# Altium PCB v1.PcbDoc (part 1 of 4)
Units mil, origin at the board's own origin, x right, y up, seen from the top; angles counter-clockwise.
Board outline 3043 x 5109 mil, 2 copper layers (Top Layer, Bottom Layer), stack 62 mil thick; 379 components, 219 nets, 963 pads, 1099 vias.
Unrouted connection lines stored in the file: 1.
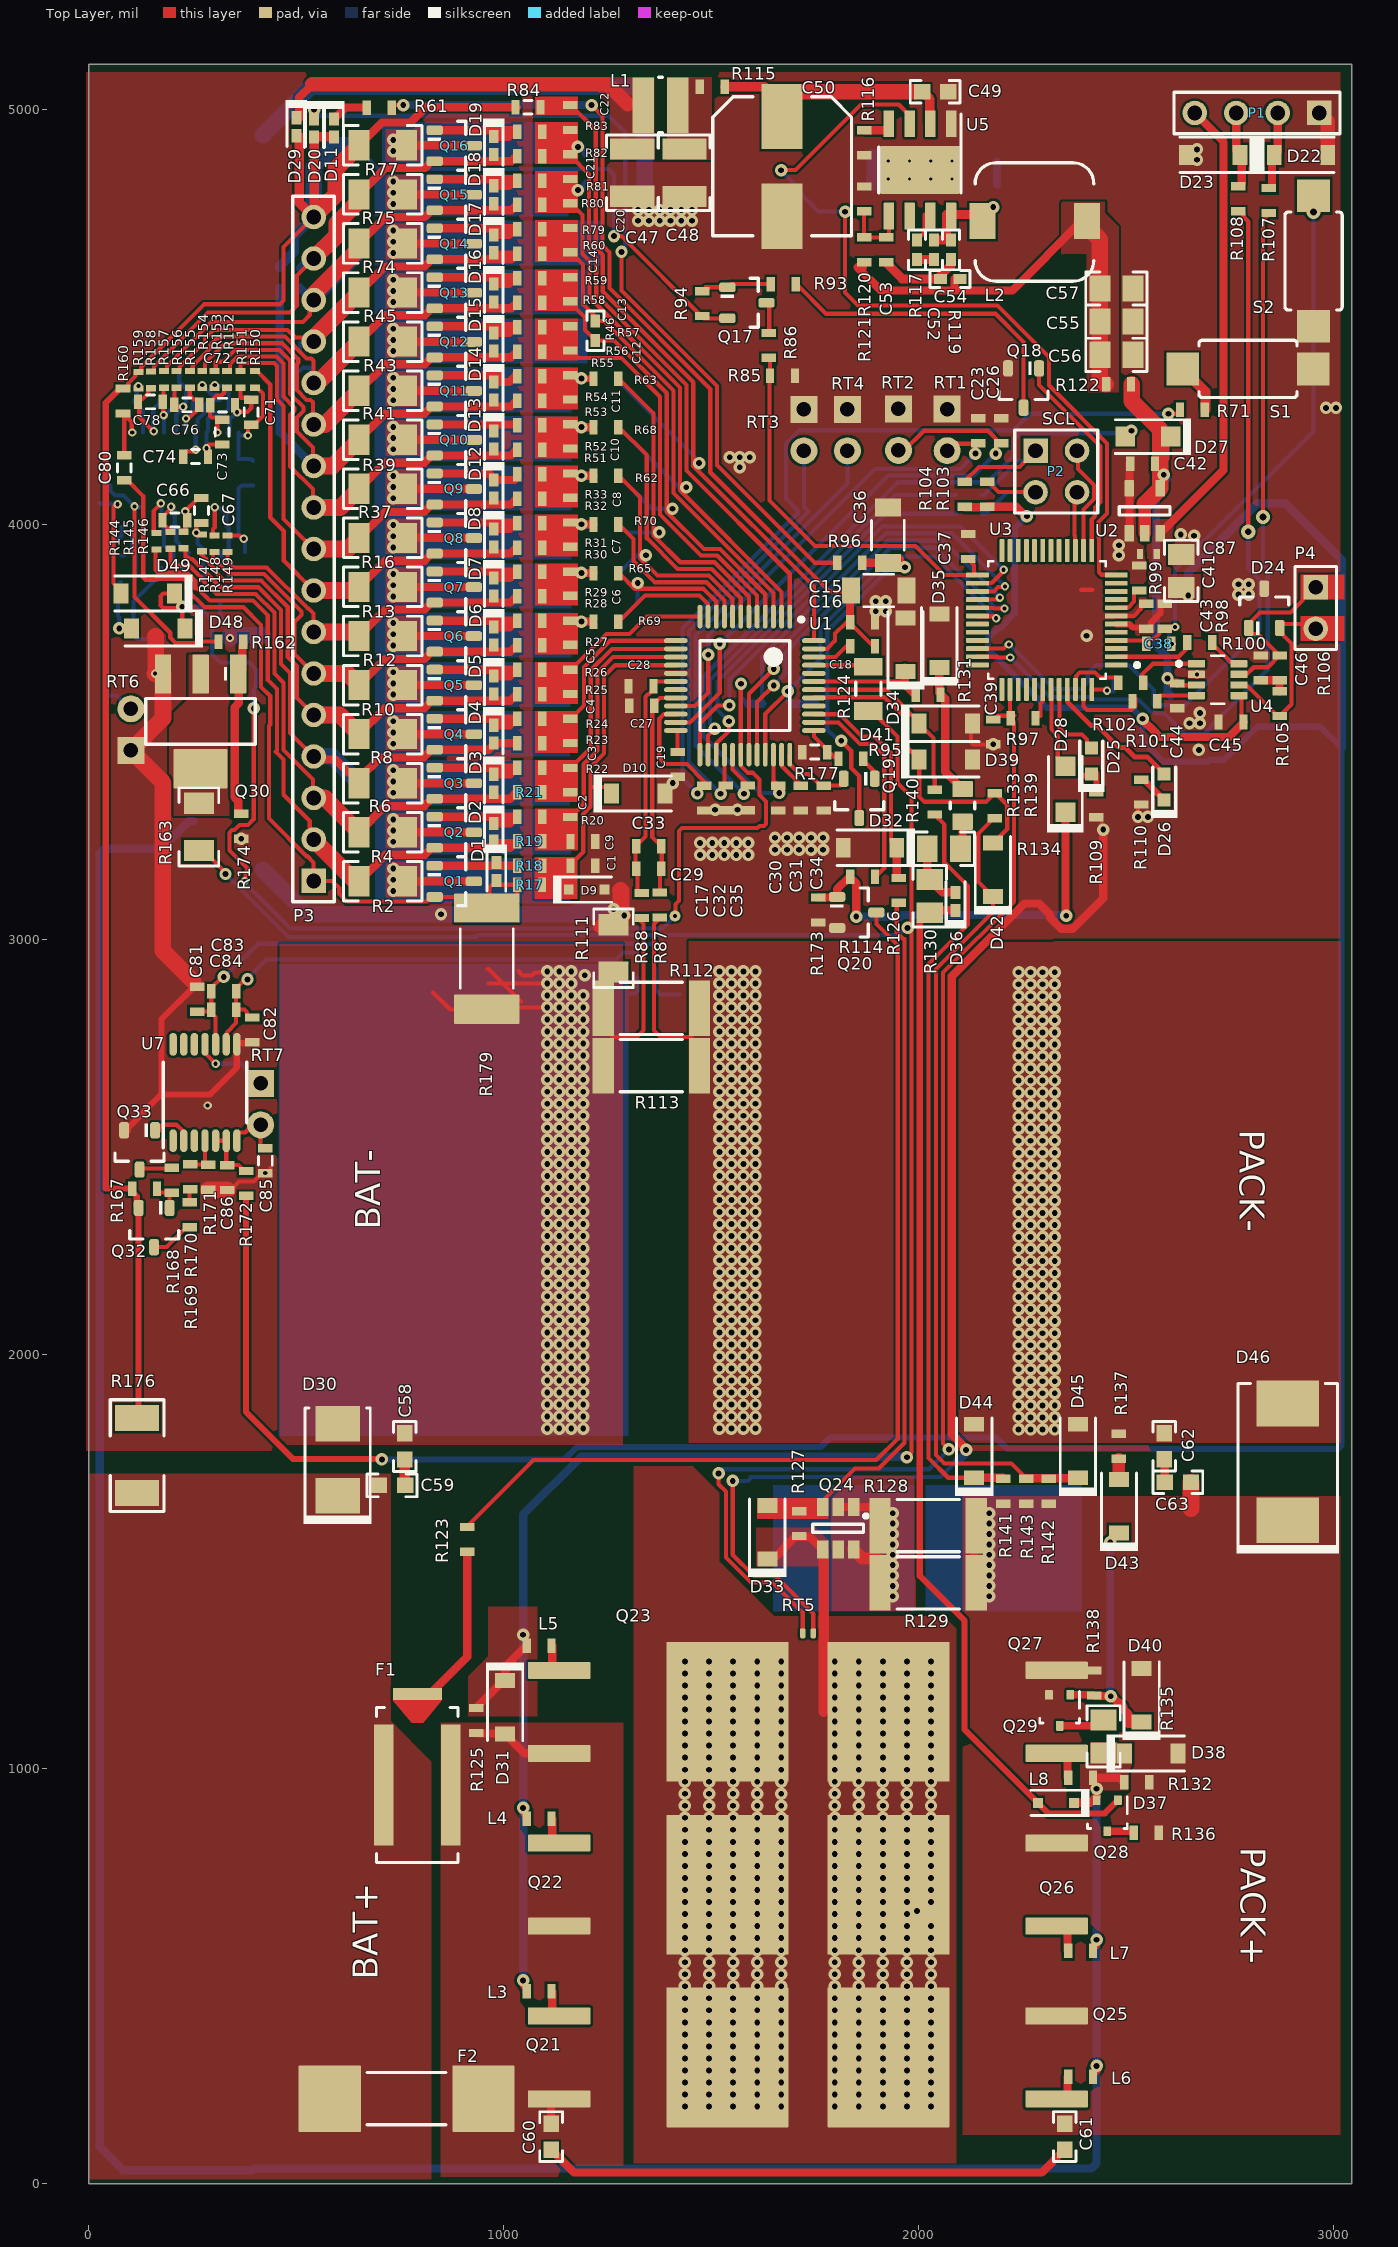
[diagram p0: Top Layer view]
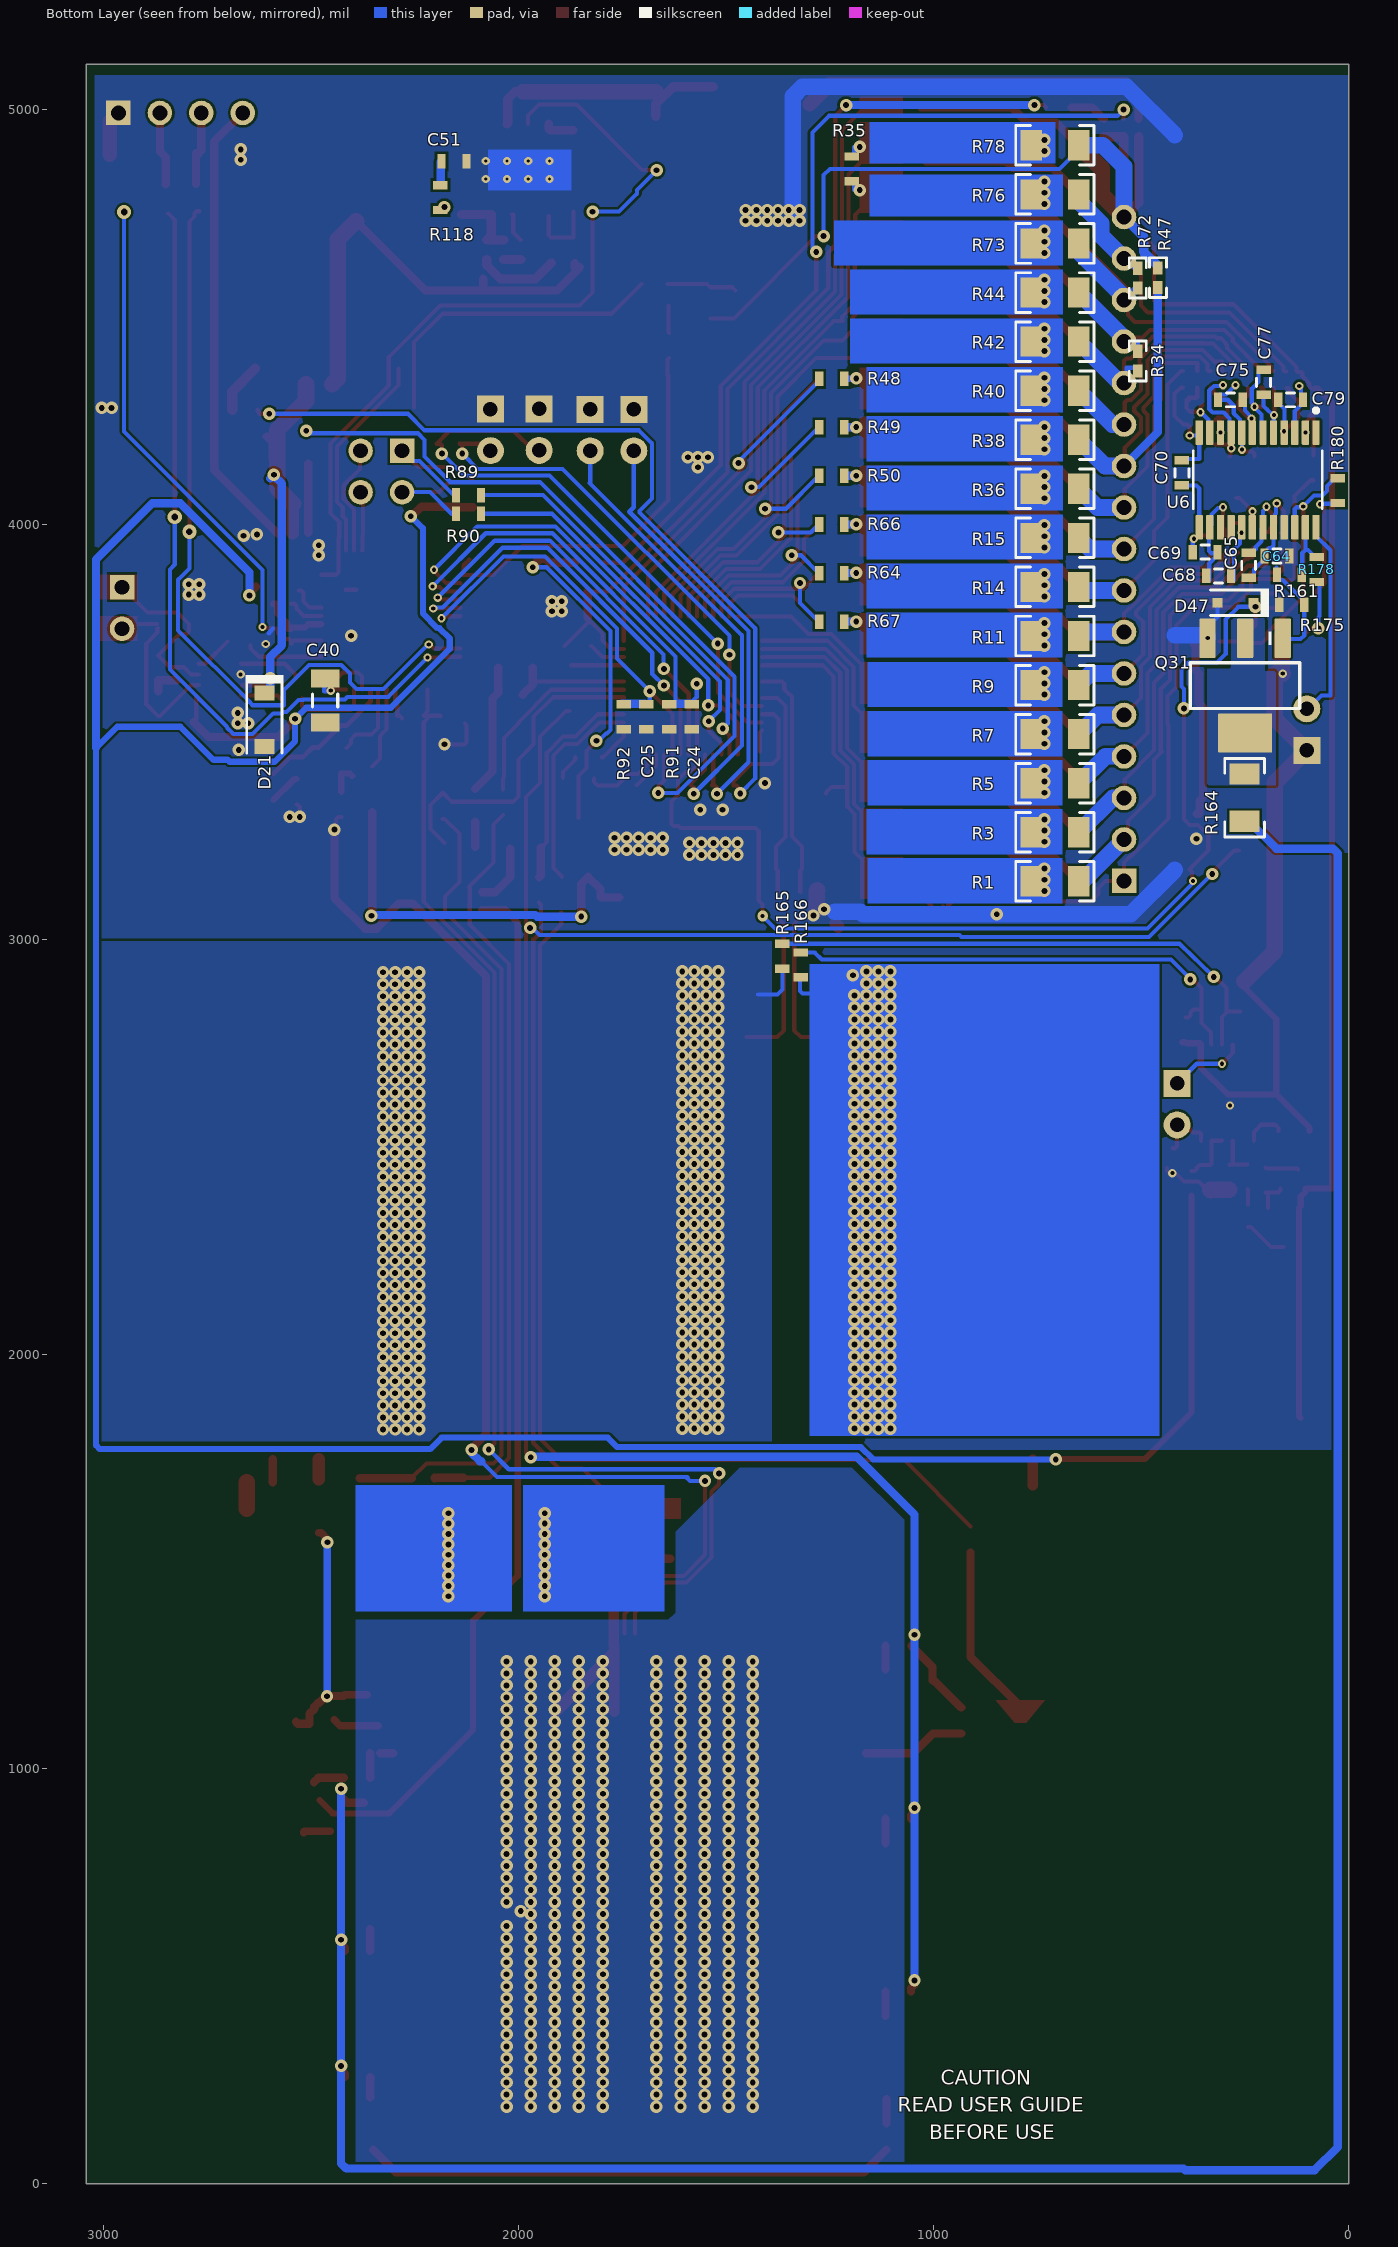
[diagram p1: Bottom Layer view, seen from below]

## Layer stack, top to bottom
Top Solder: solder mask 0.4, Solder Resist, Dk 3.5
Top Layer: signal copper 1.4
Dielectric1: core 59.2, FR-4, Dk 4.8
Bottom Layer: signal copper 1.4
Bottom Solder: solder mask 0.4, Solder Resist, Dk 3.5

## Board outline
0,0 0,5109 3043,5109 3043,0

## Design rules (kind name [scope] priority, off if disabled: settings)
AcuteAngle [All] p1: minimum=4.50000000000000E+0001 checktracksonly=FALSE
AssemblyTestPointUsage [All] p1: valid=2
BoardOutlineClearance BoardOutlineClearance_MountingHoles [OnCopper and InComponentClass('Mounting Holes')] p1 off: gap=40 ignorepadtopadclearanceinfootprint=FALSE
BoardOutlineClearance BoardOutlineClearance_Poly [OnCopper and IsPoly] p2 off: gap=25 ignorepadtopadclearanceinfootprint=FALSE
BoardOutlineClearance [OnCopper and Not InComponentClass('Logo') and not InComponentClass('FiducialMark') and not InRegion(1000,500,4000,800) and not InPoly] p3 off: gap=75 ignorepadtopadclearanceinfootprint=FALSE
Clearance Clearance_Keepouts [((IsTrack Or IsArc) And Not InPoly) And IsFree and IsKeepOut vs ((IsTrack Or IsArc) And Not InPoly) And IsFree and IsKeepOut] p1: gap=10 ignorepadtopadclearanceinfootprint=FALSE
Clearance Clearance_Poly [InPolygon] p2: gap=6 ignorepadtopadclearanceinfootprint=FALSE
Clearance Clearance_FiducialMark [IsKeepOut and InComponentClass('FiducialMark') vs IsPad and InComponentClass('FiducialMark')] p3: gap=0 ignorepadtopadclearanceinfootprint=FALSE
Clearance [All] p4: gap=6 ignorepadtopadclearanceinfootprint=FALSE
ComponentClearance ComponentClearance_MountingHoles_FiducialMarks [InComponentClass('Mounting Holes') vs InComponentClass('FiducialMark')] p1: gap=10 collisioncheckmode=3 verticalgap=10 showdistances=FALSE
ComponentClearance ComponentClearance_Shunt [InComponentClass('Header') vs InComponentClass('Shunt')] p2: gap=10 collisioncheckmode=3 verticalgap=10 showdistances=FALSE
ComponentClearance ComponentClearance_Logo [InComponentClass('Logo')] p3: gap=50 collisioncheckmode=3 verticalgap=10 showdistances=FALSE
ComponentClearance ComponentClearance_ScrewToNut [(HasFootprint('NY PMS 440 0025 PH')) vs (HasFootprint('Keystone_1902C'))] p4: gap=5 collisioncheckmode=3 verticalgap=10 showdistances=FALSE
ComponentClearance ComponentClearance_MountingHoles [InComponentClass('Mounting Holes')] p5: gap=6 collisioncheckmode=3 verticalgap=100000 showdistances=FALSE
ComponentClearance ComponentClearance_SmallPassives [HasFootprint('0201*') or HasFootprint('0402*') or HasFootprint('0508') or HasFootprint('0603*') or HasFootprint('0612') or HasFootprint('0805*') or HasFootprint('0815*') or HasFootprint('0830*') or HasFootprint('1206*') or HasFootprint('1210*') or HasFootprint('1808*') or HasFootprint('1812*') or HasFootprint('1825*') or HasFootprint('2010*') or HasFootprint('2220*') or HasFootprint('2225*') or HasFootprint('2512*') or HasFootprint('2728*') or HasFootprint('3518*') vs HasFootprint('0201*') or HasFootprint('0402*') or HasFootprint('0508') or HasFootprint('0603*') or HasFootprint('0612') or HasFootprint('0805*') or HasFootprint('0815*') or HasFootprint('0830*') or HasFootprint('1206*') or HasFootprint('1210*') or HasFootprint('1808*') or HasFootprint('1812*') or HasFootprint('1825*') or HasFootprint('2010*') or HasFootprint('2220*') or HasFootprint('2225*') or HasFootprint('2512*') or HasFootprint('2728*') or HasFootprint('3518*')] p6: gap=6 collisioncheckmode=3 verticalgap=10 showdistances=FALSE
ComponentClearance ComponentClearance_THtoSMT [IsThruComponent vs IsSMTComponent] p7: gap=6 collisioncheckmode=3 verticalgap=30 showdistances=FALSE
ComponentClearance ComponentClearance_THtoTH [IsThruComponent vs IsThruComponent] p8: gap=10 collisioncheckmode=3 verticalgap=30 showdistances=FALSE
ComponentClearance [All] p9: gap=4 collisioncheckmode=3 verticalgap=100000 showdistances=FALSE
DiffPairsRouting [All] p1: maxlimit=100 minlimit=10 mostfreqgap=10 substack1={15AE82B9-5E42-45CF-8A33-7C54FC62AE9B} toplayer_{15ae82b9-5e42-45cf-8a33-7c54fc62ae9b}_minwidth=15 toplayer_{15ae82b9-5e42-45cf-8a33-7c54fc62ae9b}_maxwidth=15 toplayer_{15ae82b9-5e42-45cf-8a33-7c54fc62ae9b}_prefwidth=15 bottomlayer_{15ae82b9-5e42-45cf-8a33-7c54fc62ae9b}_minwidth=15 bottomlayer_{15ae82b9-5e42-45cf-8a33-7c54fc62ae9b}_maxwidth=15 bottomlayer_{15ae82b9-5e42-45cf-8a33-7c54fc62ae9b}_prefwidth=15 toplayer_minwidth=15 toplayer_maxwidth=15 toplayer_prefwidth=15 bottomlayer_minwidth=15 bottomlayer_maxwidth=15 bottomlayer_prefwidth=15 maxuncoupledlength=1000
FabricationTestPointUsage TestPointUsage [All] p1: valid=2 allowmultiple=FALSE
FabricationTestpoint Testpoint [All] p1: side=3 testpointundercomponent=TRUE minsize=40 maxsize=100 preferedsize=60 minholesize=0 maxholesize=40 preferedholesize=32 testpointgrid=1 allowsidetop=TRUE allowsidebottom=TRUE usegrid=TRUE gridtolerance=0.01
FanoutControl Fanout_LCC [IsLCC] p1: bgadir=Out bgaviamode=Centered fanoutstyle=Auto fanoutdirection=Alternating viagrid=1 // Fanout_LCC (Default Rule)
FanoutControl Fanout_BGA [IsBGA] p2: bgadir=Out bgaviamode=Centered fanoutstyle=Auto fanoutdirection=Alternating viagrid=1 // Fanout_BGA (Default Rule)
FanoutControl Fanout_Default [All] p4: bgadir=Out bgaviamode=Centered fanoutstyle=Auto fanoutdirection=Alternating viagrid=1 // Fanout_Default (Default Rule)
FanoutControl Fanout_Small [(CompPinCount < 5)] p5: bgadir=Out bgaviamode=Centered fanoutstyle=Auto fanoutdirection=OutThenIn viagrid=1 // Fanout_Small (Default Rule)
HoleSize [All] p1: absolutevalues=TRUE maxlimit=251 minlimit=7.87 maxpercent=80.000 minpercent=20.000
MinimumAnnularRing MinimumAnnularRing_ThermalPadVias [IsVia and InAnyComponent] p1: minimumring=5.91
MinimumAnnularRing [All] p2: minimumring=5
MinimumSolderMaskSliver MinimumSolderMaskSliver_Logo [InComponentClass('Logo') vs InComponentClass('Logo')] p1 off: minsoldermaskwidth=0.7
MinimumSolderMaskSliver [All] p2 off: minsoldermaskwidth=3.94
PlaneConnect [All] p1: planeconnectstyle=Relief reliefexpansion=10 reliefentries=4 reliefconductorwidth=10 reliefairgap=10
PolygonConnect [All] p1: connectstyle=Direct reliefconductorwidth=10 reliefentries=4 polygonreliefangle="90 Angle" airgapwidth=10
RoutingVias ThermalPadVias [IsVia and InAnyComponent] p1: holewidth=7.87 width=19.68 viastyle="Through Hole" minholewidth=7.87 minwidth=19.68 maxholewidth=12.99 maxwidth=23.62
RoutingVias [All] p2: holewidth=16 width=34 viastyle="Through Hole" minholewidth=6 minwidth=20 maxholewidth=40 maxwidth=65
SilkToBoardRegionClearance [Not ((IsComment or IsDesignator) And (Hide <> 'False')) and not InRegion(1000,500,4000,800)] p1:
SilkToSilkClearance SilkToSilkClearance_Pb-FreeLogo [(HasFootprint('Pb-Free_Overlay_Medium') OR HasFootprint('Pb-Free_Overlay_Small')) vs (HasFootprint('Pb-Free_Overlay_Medium') OR HasFootprint('Pb-Free_Overlay_Small'))] p1 off: silktosilkclearance=1
SilkToSilkClearance [All] p2 off: silktosilkclearance=4
SilkToSolderMaskClearance SilkToComponentPadClearance [(IsPad or IsFill or IsRegion) and InAnycomponent] p1 off: minsilkscreentomaskgap=5 clearancetoexposedcopper=TRUE
SilkToSolderMaskClearance "Silk to Solder Mask Opening" [All] p2 off: minsilkscreentomaskgap=4 clearancetoexposedcopper=FALSE
SolderMaskExpansion [All] p1: expansion=1.97 istentingtop=FALSE
UnRoutedNet [All] p1: checkbadconnections=TRUE
Width [All] p1: maxlimit=100 minlimit=6 preferedwidth=10 substack1={15AE82B9-5E42-45CF-8A33-7C54FC62AE9B} checkconnectedcopper=TRUE
14 further rules are at their usual default settings.

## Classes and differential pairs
component class "High level sch": D27 D28 P3 P4 R111 R112 R113 R114 R176 R179
component class Designator: C1 C2 C3 C4 C5 C6 C7 C8 C9 C10 C11 C12 C13 C14 C15 C16 C17 C18 C19 C20 C21 C22 C23 C24 C25 C26 C27 C28 C29 C30 C31 C32 C33 C34 C35 C36 D1 D2 D3 D4 D5 D6 D7 D8 D9 D10 D11 D12 D13 D14 D15 D16 D17 D18 D19 D20 Q1 Q2 Q3 Q4 Q5 Q6 Q7 Q8 Q9 Q10 Q11 Q12 Q13 Q14 Q15 Q16 Q17 Q18 Q19 R1 R2 R3 R4 R5 R6 R7 R8 R9 R10 R11 R12 R13 R14 R15 R16 R17 R18 R19 R20 R21 R22 R23 R24 R25 R26 R27 R28 R29 R30 R31 R32 R33 R34 R35 R36 R37 R38 R39 R40 R41 R42 R43 R44 R45 R46 R47 R48 R49 R50 R51 R52 R53 R54 R55 R56 R57 R58 R59 R60 R61 R62 R63 R64 R65 R66 R67 R68 R69 R70 R71 R72 R73 R74 R75 R76 R77 R78 R79 R80 R81 R82 R83 R84 R85 R86 R87 R88 R89 R90 R91 R92 R93 R94 R95 R96 R177 RT1 RT2 RT3 RT4 S1 U1

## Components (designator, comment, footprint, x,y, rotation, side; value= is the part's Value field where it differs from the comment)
C1 "GCM188R71H224KA64D" 0603S 1190.41,3177.35 r0 top value=0.22uF
C2 "GCM188R71H224KA64D" 0603S 1159.41,3324.35 r270 top value=0.22uF
C3 "GCM188R71H224KA64D" 0603S 1159.41,3442.63 r270 top value=0.22uF
C4 "GCM188R71H224KA64D" 0603S 1159.41,3560.92 r270 top value=0.22uF
C5 "GCM188R71H224KA64D" 0603S 1159.41,3679.2 r270 top value=0.22uF
C6 "GCM188R71H224KA64D" 0603S 1159.41,3797.49 r270 top value=0.22uF
C7 "GCM188R71H224KA64D" 0603S 1159.41,3915.77 r270 top value=0.22uF
C8 "GCM188R71H224KA64D" 0603S 1159.41,4034.06 r270 top value=0.22uF
C9 "GCM188R71H224KA64D" 0603S 1190.41,3235.35 r0 top value=0.22uF
C10 "GCM188R71H224KA64D" 0603S 1159.41,4152.35 r270 top value=0.22uF
C11 "GCM188R71H224KA64D" 0603S 1159.41,4270.63 r270 top value=0.22uF
C12 "GCM188R71H224KA64D" 0603S 1159.41,4388.92 r270 top value=0.22uF
C13 "GCM188R71H224KA64D" 0603S 1159.41,4507.2 r270 top value=0.22uF
C14 "GCM188R71H224KA64D" 0603S 1159.41,4625.49 r270 top value=0.22uF
C15 "CL31B225KCHSNNE" 1206_190 1903.41,3840.35 r180 top value=2.2uF
C16 "GRM1885C2A101JA01D" 0603S 1864.41,3763.35 r180 top value=100pF
C17 "GRM1885C2A101JA01D" 0603S 1482.75,3340.08 r270 top value=100pF
C18 "C1608X7R1E105K080AB" 0603S 1864.41,3706.35 r0 top value=1uF
C19 "EMK107BB7225MA-T" 0603S 1418.75,3421.08 r270 top value=2.2uF
C20 "GCM188R71H224KA64D" 0603S 1159.41,4743.77 r270 top value=0.22uF
C21 "GCM188R71H224KA64D" 0603S 1159.41,4862.06 r270 top value=0.22uF
C22 "GCM188R71H224KA64D" 0603S 1159.41,4980.35 r270 top value=0.22uF
C23 "GRM188R71H471KA01D" 0603S 2143.41,4225.36 r90 top value=470pF
C24 "GRM1885C2A101JA01D" 0603S 1583.41,3535.84 r270 bottom value=100pF
C25 "GRM1885C2A101JA01D" 0603S 1692.79,3535.84 r270 bottom value=100pF
C26 "GRM188R71H471KA01D" 0603S 2198.41,4225.36 r90 top value=470pF
C27 "GRM188R71H104KA93D" 0603S 1332.41,3562.35 r0 top value=0.1uF
C28 "GRM188R71H104KA93D" 0603S 1330.41,3609.35 r0 top value=0.1uF
C29 "GRM188R71H104KA93D" 0603S 1348.91,3169.35 r0 top value=0.1uF
C30 "GCM188R71C105KA64D" 0603S 1660.75,3340.08 r270 top value=1uF
C31 "GCM188R71C105KA64D" 0603S 1715.75,3340.08 r270 top value=1uF
C32 "GRM188R71H471KA01D" 0603S 1534.41,3340.35 r270 top value=470pF
C33 "GRM1885C2A101JA01D" 0603S 1348.91,3223.35 r0 top value=100pF
C34 "GRM188R71H223KA01D" 0603S 1770.41,3340.08 r270 top value=0.022uF
C35 "GRM188R71H471KA01D" 0603S 1587.41,3340.35 r270 top value=470pF
C36 "C3216X7R2A105K160AA" 1206_180 1925.41,3973.35 r90 top value=1uF
C37 "GRM188R71H471KA01D" 0603S 2119.41,3946.35 r270 top value=470pF
C38 "GRM1885C1H102JA01D" 0603S 2578.48,3711.42 r0 top value=1000pF
C39 "GRM188R71H471KA01D" 0603S 2179.25,3499.54 r270 top value=470pF
C40 "12063C474KAT2A" 1206L 2467,3575.15 r270 bottom value=0.47uF
C41 "CL21B106KOQNNNE" 0805_HV 2632.41,3887.35 r270 top value=10uF
C42 "EMK107BB7225MA-T" 0603S 2539.41,4146.35 r180 top value=2.2uF
C43 "GRM188R71H104KA93D" 0603S 2548.41,3778.35 r270 top value=0.1uF
C44 "GRM188R71H104KA93D" 0603S 2622.41,3586.35 r270 top value=0.1uF
C45 "GRM188R71H104KA93D" 0603S 2752.41,3523.35 r180 top value=0.1uF
C46 "GRM188R71H104KA93D" 0603S 2824.41,3653.68 r270 top value=0.1uF
C47 "C3225X7S2A475K200AE" 1210 1309.41,4847.35 r270 top value=4.7uF
C48 "C3225X7S2A475K200AE" 1210 1435,4847 r270 top value=4.7uF
C49 "GRM188R72A104KA35D" 0603 2039.41,5042.35 r0 top value=0.1uF
C50 "UUX2A100MNL1GS" UUX_800x620 1670.41,4862.76 r270 top value=10uF
C51 "GRM1885C1H560JA01D" 0603S 2156.41,4874.35 r180 bottom value=56pF
C52 "GRM155R71H222KA01D" 0402 2036.41,4661.35 r90 top value=2200pF
C53 "GRM1885C1H101JA01D" 0603S 1921.41,4661.35 r90 top value=100pF
C54 "GRM155R71H152KA01D" 0402 2075.41,4591.35 r180 top value=1500pF
C55 "GRM21BR71C475KA73L" 0805_HV 2476.41,4488.35 r0 top value=4.7uF
C56 "GRM21BR71C475KA73L" 0805_HV 2476.41,4408.35 r0 top value=4.7uF
C57 "GRM21BR71C475KA73L" 0805_HV 2476.41,4568.35 r0 top value=4.7uF
C58 "GRM188R72A104KA35D" 0603 761.41,1777.35 r90 top value=0.1uF
C59 "GRM188R72A104KA35D" 0603 730.41,1683.35 r0 top value=0.1uF
C60 "GRM188R72A104KA35D" 0603 1113.75,113.85 r90 top value=0.1uF
C61 "GRM188R72A104KA35D" 0603 2351.61,113.85 r270 top value=0.1uF
C62 "GRM188R72A104KA35D" 0603 2591.28,1777.86 r90 top value=0.1uF
C63 "GRM188R72A104KA35D" 0603 2624.41,1691.35 r180 top value=0.1uF
C64 "885012206095" 0603S 173,3923.44 r180 bottom value=0.1uF
C65 "885012206095" 0603S 241,3901 r270 bottom value=0.1uF
C66 "885012206095" 0603S 207,4010 r180 top value=0.1uF
C67 "885012206095" 0603S 271,4033 r90 top value=0.1uF
C68 "885012206095" 0603S 313.54,3875.57 r180 bottom value=0.1uF
C69 "885012206095" 0603S 346,3933 r180 bottom value=0.1uF
C70 "885012206095" 0603S 402,4124 r270 bottom value=0.1uF
C71 "885012206095" 0603S 391,4270 r270 top value=0.1uF
C72 "885012206095" 0603S 322,4287 r0 top value=0.1uF
C73 "885012206095" 0603S 321,4222 r90 top value=0.1uF
C74 "885012206095" 0603S 257,4163 r0 top value=0.1uF
C75 "885012206095" 0603S 285,4300 r0 bottom value=0.1uF
C76 "885012206095" 0603S 235.84,4287.73 r0 top value=0.1uF
C77 "885012206095" 0603S 205,4342 r90 bottom value=0.1uF
C78 "885012206095" 0603S 148,4295 r0 top value=0.1uF
C79 "885012206095" 0603S 140,4300 r0 bottom value=0.1uF
C80 "GCJ188R72A104KA01D" 0603S 85,4136 r270 top value=0.1uF
C81 "GRM188R71H104KA93D" 0603S 260.59,2855.35 r270 top value=0.1uF
C82 "GRM188R71H104KA93D" 0603S 393.59,2781.35 r90 top value=0.1uF
C83 "GRM188R71H104KA93D" 0603S 324.59,2874.35 r180 top value=0.1uF
C84 "GRM1885C2A101JA01D" 0603S 324.59,2830.35 r180 top value=100pF
C85 "GRM185C81A105KE36D" 0603S 425,2466 r270 top value=1uF
C86 "GRM188R71H104KA93D" 0603S 333.59,2425.35 r270 top value=0.1uF
C87 "GRM155R61A105KE15D" 0402S 2553.41,3928.35 r180 top value=1uF
D1 "BZT52C5V6T-7" SOD-523 982,3163 r270 top value=5.6V
D2 "BZT52C5V6T-7" SOD-523 975.41,3257.55 r270 top value=5.6V
D3 "BZT52C5V6T-7" SOD-523 975.41,3375.75 r270 top value=5.6V
D4 "BZT52C5V6T-7" SOD-523 975.41,3493.95 r270 top value=5.6V
D5 "BZT52C5V6T-7" SOD-523 975.41,3612.15 r270 top value=5.6V
D6 "BZT52C5V6T-7" SOD-523 975.41,3730.35 r270 top value=5.6V
D7 "BZT52C5V6T-7" SOD-523 975.41,3848.55 r270 top value=5.6V
D8 "BZT52C5V6T-7" SOD-523 975.41,3966.75 r270 top value=5.6V
D9 "BAT42WS-7-F" SOD-323 1199.41,3119.35 r0 top value=30V
D10 "MMSZ4685T1G" SOD-123 1324,3351 r0 top value=3.6V
D11 "BAS516,115" SOD-523 590.41,4955.35 r270 top value=100V
D12 "BZT52C5V6T-7" SOD-523 975.41,4084.95 r270 top value=5.6V
D13 "BZT52C5V6T-7" SOD-523 975.41,4203.15 r270 top value=5.6V
D14 "BZT52C5V6T-7" SOD-523 975.41,4321.35 r270 top value=5.6V
D15 "BZT52C5V6T-7" SOD-523 975.41,4439.55 r270 top value=5.6V
D16 "BZT52C5V6T-7" SOD-523 975.41,4557.75 r270 top value=5.6V
D17 "BZT52C5V6T-7" SOD-523 975.41,4675.95 r270 top value=5.6V
D18 "BZT52C5V6T-7" SOD-523 975.41,4794.15 r270 top value=5.6V
D19 "BZT52C5V6T-7" SOD-523 975.41,4912.35 r270 top value=5.6V
D20 "BAS516,115" SOD-523 542.41,4955.35 r270 top value=100V
D21 "MMSZ4690T1G" SOD-123 2613.41,3528.35 r270 bottom value=5.6V
D22 "MMSZ4685T1G" SOD-123 2921.11,4890.3 r0 top value=3.6V
D23 "MMSZ4685T1G" SOD-123 2709.11,4890.3 r180 top value=3.6V
D24 "NUP3105LT1G" SOT-23 2832.41,3797.35 r90 top value=32V
D25 "150060RS75000" WL-SMCW_RED 2415.68,3429.62 r90 top value=Red
D26 "150060RS75000" WL-SMCW_RED 2591.41,3366.84 r90 top value=Red
D27 "PMEG2010AEH,115" SOD-123F 2552.41,4211.35 r180 top value=20V
D28 "PMEG2010AEH,115" SOD-123F 2353.41,3361.35 r90 top value=20V
D29 "BAS516,115" SOD-523 500,4958 r270 top value=100V
D30 "SMBJ60A-13-F" SMB 599.41,1745.35 r90 top value=60V
D31 "MMSZ5246B-7-F" SOD-123 1002.93,1148.85 r270 top value=16V
D32 "MMSZ5267BT1G" SOD-123 1882.41,3220.35 r180 top value=75V
D33 "MMSZ5246B-7-F" SOD-123 1634.89,1570.82 r90 top value=16V
D34 "MMSZ5263BT1G" SOD-123 1968,3709.47 r90 top value=56V
D35 "BAT46W-7-F" SOD-123 2049.41,3719.35 r90 top value=100V
D36 "BAS516,115" SOD-523 2088.41,3091.05 r90 top value=100V
D37 "BZT52C5V1S-7-F" SOD-323 2330.41,918.35 r180 top value=5.1V
D38 "MMSZ5246B-7-F" SOD-123 2560.41,1037.35 r0 top value=16V
D39 "MMSZ5267BT1G" SOD-123 2065.41,3433.35 r0 top value=75V
D40 "MMSZ5246B-7-F" SOD-123 2537,1178 r90 top value=16V
D41 "MMSZ5267BT1G" SOD-123 2065.41,3519.35 r0 top value=75V
D42 "BAT46W-7-F" SOD-123 2178.41,3167.35 r90 top value=100V
D43 "BAT46W-7-F" SOD-123 2482.41,1633.35 r90 top value=100V
D44 "BAT46W-7-F" SOD-123 2133.41,1766.35 r90 top value=100V
D45 "BAT46W-7-F" SOD-123 2383.41,1766.35 r90 top value=100V
D46 "ES3D-E3/57T" SMC 2889.41,1740.35 r90 top value=200V
D47 "CMDZ4L7 TR" SOD-323 273,3811 r0 bottom value=4.7V
D48 "BAT46W-7-F" SOD-123 167,3749 r180 top value=100V
D49 "BAT46W-7-F" SOD-123 142,3833 r180 top value=100V
F1 "NC" FUSE_SFK-xx30x 791.41,961.35 r270 top
F2 "0678L9300-02" Fuse_0678L 765.41,205.35 r180 top
L1 "74438335010" WE-MAPI_3015 1377.41,5010.35 r0 top value=1uH
L2 "744777168" WE-PD_7345 2279.41,4730.35 r0 top value=68uH
L3 "74279265" 0603S 1084.93,463.85 r0 top value="600 ohm"
L4 "74279265" 0603S 1084.93,880.35 r0 top value="600 ohm"
L5 "74279265" 0603S 1084.93,1296.85 r0 top value="600 ohm"
L6 "74279265" 0603S 2389.93,257.85 r180 top value="600 ohm"
L7 "74279265" 0603S 2389.93,561.85 r180 top value="600 ohm"
L8 "74279265" 0603S 2389.93,978.85 r180 top value="600 ohm"
P1 "Header 4" HDR1X4 2965.11,4991.3 r180 top
P2 "Header 2X2" HDR2X2 2281.41,4177.35 r270 top
P3 "Header 17" HDR1X17 541.41,3140.35 r90 top
P4 "Header 2" HDR1X2 2956.41,3848.35 r270 top
Q1 "DMG2302UK-7" SOT-23 880.41,3139.35 r0 top value=20V
Q2 "DMG2302UK-7" SOT-23 880.41,3257.55 r0 top value=20V
Q3 "DMG2302UK-7" SOT-23 880.41,3375.75 r0 top value=20V
Q4 "DMG2302UK-7" SOT-23 880.41,3493.95 r0 top value=20V
Q5 "DMG2302UK-7" SOT-23 880.41,3612.15 r0 top value=20V
Q6 "DMG2302UK-7" SOT-23 880.41,3730.35 r0 top value=20V
Q7 "DMG2302UK-7" SOT-23 880.41,3848.55 r0 top value=20V
Q8 "DMG2302UK-7" SOT-23 880.41,3966.75 r0 top value=20V
Q9 "DMG2302UK-7" SOT-23 880.41,4084.95 r0 top value=20V
Q10 "DMG2302UK-7" SOT-23 880.41,4203.15 r0 top value=20V
Q11 "DMG2302UK-7" SOT-23 880.41,4321.35 r0 top value=20V
Q12 "DMG2302UK-7" SOT-23 880.41,4439.55 r0 top value=20V
Q13 "DMG2302UK-7" SOT-23 880.41,4557.75 r0 top value=20V
Q14 "DMG2302UK-7" SOT-23 880.41,4675.95 r0 top value=20V
Q15 "DMG2302UK-7" SOT-23 880.41,4794.15 r0 top value=20V
Q16 "DMG2302UK-7" SOT-23 880.41,4912.35 r0 top value=20V
Q17 "ZXMP10A13FTA" SOT-23 1585.71,4533.67 r0 top value=-100V
Q18 "BSS123" SOT-23 2252.41,4328.35 r270 top value=100V
Q19 "ZXTN25100BFHTA" SOT-23 1856.41,3339.35 r270 top value="100 V"
Q20 "DMN10H220L-7" SOT-23 1850.41,3064.35 r0 top value=100V
Q21 "CSD19536KTT" KTT0002A 1404.83,304.74 r0 top value=100V
Q22 "CSD19536KTT" KTT0002A 1404.83,721.24 r0 top value=100V
Q23 "CSD19536KTT" KTT0002A 1404.83,1137.74 r0 top value=100V
Q24 "FDC3535" SSOT-6 1805.41,1580.17 r270 top value=-80V
Q25 "CSD19536KTT" KTT0002A 2060.53,304.84 r180 top value=100V
Q26 "CSD19536KTT" KTT0002A 2060.53,721.34 r180 top value=100V
Q27 "CSD19536KTT" KTT0002A 2060.53,1137.84 r180 top value=100V
Q28 "DMG1013UW-7" SOT-323 2454.41,887.35 r270 top value=-20V
Q29 "2N7002W-7-F" SOT-323 2339.41,1141.35 r270 top value=60V
Q30 "FDT86113LZ" SOT-223 269,3525 r270 top value=100V
Q31 "FDT86113LZ" SOT-223 249.69,3611 r270 bottom value=100V
Q32 "ZXMP10A13FTA" SOT-23 157,2305 r270 top value=-100V
Q33 "BSS123" SOT-23 122,2492 r270 top value=100V
R1 "CRCW120680R6FKEA" 1206 707.94,3139.35 r0 bottom value=80.6
R2 "CRCW120680R6FKEA" 1206 707.94,3139.35 r0 top value=80.6
R3 "CRCW120680R6FKEA" 1206 707.94,3257.6 r0 bottom value=80.6
R4 "CRCW120680R6FKEA" 1206 707.94,3257.6 r0 top value=80.6
R5 "CRCW120680R6FKEA" 1206 707.94,3375.86 r0 bottom value=80.6
R6 "CRCW120680R6FKEA" 1206 707.94,3375.86 r0 top value=80.6
R7 "CRCW120680R6FKEA" 1206 707.94,3494.12 r0 bottom value=80.6
R8 "CRCW120680R6FKEA" 1206 707.94,3494.12 r0 top value=80.6
R9 "CRCW120680R6FKEA" 1206 707.94,3612.38 r0 bottom value=80.6
R10 "CRCW120680R6FKEA" 1206 707.94,3612.38 r0 top value=80.6
R11 "CRCW120680R6FKEA" 1206 707.94,3730.63 r0 bottom value=80.6
R12 "CRCW120680R6FKEA" 1206 707.94,3730.63 r0 top value=80.6
R13 "CRCW120680R6FKEA" 1206 707.94,3848.89 r0 top value=80.6
R14 "CRCW120680R6FKEA" 1206 707.94,3848.89 r0 bottom value=80.6
R15 "CRCW120680R6FKEA" 1206 707.94,3967.15 r0 bottom value=80.6
R16 "CRCW120680R6FKEA" 1206 707.94,3967.15 r0 top value=80.6
R17 "CRCW0603100RFKEA" 0603S 1062,3131 r0 top value=100
R18 "CRCW060310K0JNEA" 0603S 1062.41,3177.31 r0 top value=10k
R19 "CRCW0603100RFKEA" 0603S 1062.41,3236.28 r0 top value=100
R20 "CRCW060310K0JNEA" 0603S 1062.41,3295.25 r0 top value=10k
R21 "CRCW0603100RFKEA" 0603S 1062.41,3354.22 r0 top value=100
R22 "CRCW060310K0JNEA" 0603S 1062.41,3413.19 r0 top value=10k
R23 "CRCW0603100RFKEA" 0603S 1062.41,3472.15 r0 top value=100
R24 "CRCW060310K0JNEA" 0603S 1062.41,3531.12 r0 top value=10k
R25 "CRCW0603100RFKEA" 0603S 1062.41,3590.09 r0 top value=100
R26 "CRCW060310K0JNEA" 0603S 1062.41,3649.06 r0 top value=10k
R27 "CRCW0603100RFKEA" 0603S 1062.41,3708.02 r0 top value=100
R28 "CRCW060310K0JNEA" 0603S 1062.41,3766.99 r0 top value=10k
R29 "CRCW0603100RFKEA" 0603S 1062.41,3825.96 r0 top value=100
R30 "CRCW060310K0JNEA" 0603S 1062.41,3884.93 r0 top value=10k
R31 "CRCW0603100RFKEA" 0603S 1062.41,3943.89 r0 top value=100
R32 "CRCW060310K0JNEA" 0603S 1062.41,4002.86 r0 top value=10k
R33 "CRCW0603100RFKEA" 0603S 1062.41,4061.83 r0 top value=100
R34 "CRCW04020000Z0ED" 0402 508.41,4393.35 r90 bottom value=0
R35 "CRCW06030000Z0EA" 0603S 1197.41,4856.35 r270 bottom value=0
R36 "CRCW120680R6FKEA" 1206 707.94,4085.4 r0 bottom value=80.6
R37 "CRCW120680R6FKEA" 1206 707.94,4085.4 r0 top value=80.6
R38 "CRCW120680R6FKEA" 1206 707.94,4203.66 r0 bottom value=80.6
R39 "CRCW120680R6FKEA" 1206 707.94,4203.66 r0 top value=80.6
R40 "CRCW120680R6FKEA" 1206 707.94,4321.92 r0 bottom value=80.6
R41 "CRCW120680R6FKEA" 1206 707.94,4321.92 r0 top value=80.6
R42 "CRCW120680R6FKEA" 1206 707.94,4440.18 r0 bottom value=80.6
R43 "CRCW120680R6FKEA" 1206 707.94,4440.18 r0 top value=80.6
R44 "CRCW120680R6FKEA" 1206 707.94,4558.43 r0 bottom value=80.6
R45 "CRCW120680R6FKEA" 1206 707.94,4558.43 r0 top value=80.6
R46 "CRCW04020000Z0ED" 0402 1220.41,4466.35 r90 top value=0
R47 "CRCW04020000Z0ED" 0402 460,4594.38 r270 bottom value=0
R48 "CRCW06030000Z0EA" 0603S 1245.91,4350.35 r0 bottom value=0
R49 "CRCW06030000Z0EA" 0603S 1245.91,4233.35 r0 bottom value=0
R50 "CRCW06030000Z0EA" 0603S 1245.91,4116.35 r0 bottom value=0
R51 "CRCW060310K0JNEA" 0603S 1062.41,4120.8 r0 top value=10k
R52 "CRCW0603100RFKEA" 0603S 1062.41,4179.77 r0 top value=100
R53 "CRCW060310K0JNEA" 0603S 1062.41,4238.73 r0 top value=10k
R54 "CRCW0603100RFKEA" 0603S 1062.41,4297.7 r0 top value=100
R55 "CRCW060310K0JNEA" 0603S 1062.41,4356.67 r0 top value=10k
R56 "CRCW0603100RFKEA" 0603S 1062.41,4415.64 r0 top value=100
R57 "CRCW060310K0JNEA" 0603S 1062.41,4474.6 r0 top value=10k
R58 "CRCW0603100RFKEA" 0603S 1062.41,4533.57 r0 top value=100
R59 "CRCW060310K0JNEA" 0603S 1062.41,4592.54 r0 top value=10k
R60 "CRCW0603100RFKEA" 0603S 1062.41,4651.51 r0 top value=100
R61 "CRCW0603100RFKEA" 0603S 699.41,5004.35 r0 top value=100
R62 "CRCW06030000Z0EA" 0603S 1245.91,4116.32 r0 top value=0
R63 "CRCW06030000Z0EA" 0603S 1245.91,4350.35 r0 top value=0
R64 "CRCW06030000Z0EA" 0603S 1245.91,3882.35 r0 bottom value=0
R65 "CRCW06030000Z0EA" 0603S 1245.91,3882.36 r180 top value=0
R66 "CRCW06030000Z0EA" 0603S 1245.91,3999.35 r0 bottom value=0
R67 "CRCW06030000Z0EA" 0603S 1245.91,3765.35 r0 bottom value=0
R68 "CRCW06030000Z0EA" 0603S 1245.91,4233.4 r180 top value=0
R69 "CRCW06030000Z0EA" 0603S 1245.91,3765.35 r180 top value=0
R70 "CRCW06030000Z0EA" 0603S 1245.91,3999.37 r180 top value=0
R71 "CRCW060310K0JNEA" 0603S 2659.41,4276.35 r180 top value=10k
R72 "CRCW04020000Z0ED" 0402 508.41,4593.35 r90 bottom value=0
R73 "CRCW120680R6FKEA" 1206 707.94,4676.69 r0 bottom value=80.6
R74 "CRCW120680R6FKEA" 1206 707.94,4676.69 r0 top value=80.6
R75 "CRCW120680R6FKEA" 1206 707.94,4794.95 r0 top value=80.6
R76 "CRCW120680R6FKEA" 1206 707.94,4794.95 r0 bottom value=80.6
R77 "CRCW120680R6FKEA" 1206 707.94,4913.21 r0 top value=80.6
R78 "CRCW120680R6FKEA" 1206 707.94,4913.21 r0 bottom value=80.6
R79 "CRCW060310K0JNEA" 0603S 1062.41,4710.47 r0 top value=10k
R80 "CRCW0603100RFKEA" 0603S 1062.41,4769.44 r0 top value=100
R81 "CRCW060310K0JNEA" 0603S 1062.41,4828.41 r0 top value=10k
R82 "CRCW0603100RFKEA" 0603S 1062.41,4887.38 r0 top value=100
R83 "CRCW060310K0JNEA" 0603S 1062.41,4946.35 r0 top value=10k
R84 "CRCW060320R0JNEA" 0603S 1058,5005 r0 top value=20
R85 "RT0603DRE0713K3L" 0603S 1671.41,4357.85 r180 top value=13.3k
R86 "RT0603DRE07665KL" 0603S 1638,4431 r90 top value=665k
R87 "CRCW0603100RFKEA" 0603S 1375.91,3082.35 r90 top value=100
R88 "CRCW0603100RFKEA" 0603S 1332,3081 r90 top value=100
R89 "CRCW0603100RFKEA" 0603S 2121.41,4070.35 r180 bottom value=100
R90 "CRCW0603100RFKEA" 0603S 2121.41,4025.35 r180 bottom value=100
R91 "CRCW060310K0JNEA" 0603S 1638.03,3535.84 r90 bottom value=10k
R92 "CRCW060310K0JNEA" 0603S 1747.41,3535.84 r90 bottom value=10k
R93 "CRCW06033M30JNEA" 0603S 1673.41,4578.85 r180 top value=3.3Meg
R94 "CRCW06031M00JNEA" 0603S 1477.71,4531.67 r270 top value=1.0Meg
R95 "CRCW0603100RFKEA" 0603S 1836.41,3435.35 r0 top value=100
R96 "RC0603FR-07249RL" 0603S 1833.41,3907.35 r180 top value=249
R97 "CRCW060310K0FKEA" 0603S 2251.25,3532.04 r0 top value=10.0k
R98 "RC0603FR-0747KL" 0603S 2592.41,3778.35 r90 top value=47.0k
R99 "RT0603BRD07100KL" 0603S 2531.41,3870.35 r270 top value=100k
R100 "CRCW0603100RFKEA" 0603S 2677,3715 r180 top value=100
R101 "CRCW0603100RFKEA" 0603S 2545,3573 r180 top value=100
R102 "CRCW0603100RFKEA" 0603S 2511,3618 r180 top value=100
R103 "CRCW060310K0JNEA" 0603S 2165.41,4072.35 r90 top value=10k
R104 "CRCW060310K0JNEA" 0603S 2110.41,4072.35 r90 top value=10k
R105 "RC0603FR-0760R4L" 0603S 2869.41,3567.68 r270 top value=60.4
R106 "RC0603FR-0760R4L" 0603S 2869.41,3653.68 r270 top value=60.4
R107 "CRCW0603100RFKEA" 0603S 2843.88,4780.3 r90 top value=100
R108 "CRCW0603100RFKEA" 0603S 2769.41,4784.35 r90 top value=100
R109 "RC0603FR-07470RL" 0603S 2428,3324 r90 top value=470
R110 "RC0603FR-07470RL" 0603S 2535.77,3354.54 r90 top value=470
R111 "MCR18EZHJ000" 1206 1264.23,2977.78 r270 top value=0
R112 "CSNL2512FT2L00" 2512 1355.41,2833.35 r0 top value=0.002
R113 "CSNL2512FT2L00" 2512 1355.41,2695.35 r0 top value=0.002
R114 "CRCW06035K10JNEA" 0603S 1864.41,3150.35 r180 top value=5.1k
R115 "CRCW0603100RFKEA" 0603S 1502,5054 r0 top value=100
R116 "CRCW060382K5FKEA" 0603S 1868.41,4919.35 r90 top value=82.5k
R117 "CRCW04020000Z0ED" 0402 1995.41,4661.35 r270 top value=0
R118 "RC0603FR-07499KL" 0603S 2189.19,4787.35 r270 bottom value=499k
R119 "RC0402FR-07523KL" 0402 2077.41,4661.35 r270 top value=523k
R120 "CRCW060363K4FKEA" 0603S 1868,4784 r270 top value=63.4k
R121 "CRCW0603200KFKEA" 0603S 1868.34,4661.35 r270 top value=200k
R122 "CRCW06030000Z0EA" 0603S 2481.41,4337.35 r180 top value=0
R123 "CRCW0603200RFKEA" 0603S 911.41,1553.35 r90 top value=200
R124 "ERJ-8ENF4990V" 1206L 1878.41,3603.35 r270 top value=499
R125 "CRCW060310M0JNEA" 0603S 933.93,1116.85 r270 top value=10Meg
R126 "RT0603BRD0749K9L" 0603S 1951.41,3117.56 r270 top value=49.9k
R127 "CRCW06031M00JNEA" 0603S 1711.52,1591.49 r270 top value=1.0Meg
R128 "RC2512JK-07510RL" 2512 2022.41,1586.35 r180 top value=510
R129 "RC2512JK-07510RL" 2512 2022.41,1448.35 r180 top value=510
R130 "RC0805JR-0756KL" 0805_HV 2026.41,3103.55 r270 top value=56k
R131 "CRCW0603100RFKEA" 0603S 2022.41,3589.35 r0 top value=100
R132 "CRCW060310M0JNEA" 0603S 2525.41,968.35 r0 top value=10Meg
R133 "CRCW0805511RFKEA" 0805_HV1 2105.41,3322.35 r270 top value=511
R134 "CRCW0805511RFKEA" 0805_HV 2060.41,3217.85 r0 top value=511
R135 "CRCW0805511RFKEA" 0805_HV 2445.41,1078.35 r90 top value=511
R136 "CRCW0603511RFKEA" 0603S 2548,846 r0 top value=511
R137 "CRCW060310K0JNEA" 0603S 2482.41,1777.86 r270 top value=10k
R138 "CRCW060310M0JNEA" 0603S 2422.41,1207.35 r270 top value=10Meg
R139 "RT0603BRD0749K9L" 0603S 2183.41,3321.35 r270 top value=49.9k
R140 "CRCW06035K10JNEA" 0603S 2038.41,3330.35 r270 top value=5.1k
R141 "RT0603BRD0749K9L" 0603S 2203.41,1669.35 r270 top value=49.9k
R142 "CRCW060320K0JNEA" 0603S 2313.41,1669.35 r270 top value=20k
R143 "CRCW060320K0JNEA" 0603S 2258.41,1669.35 r270 top value=20k
R144 "ERJ-2GEJ102X" 0402S 163,3959 r90 top value=1.0k
R145 "ERJ-2GEJ102X" 0402S 197,3961 r90 top value=1.0k
R146 "ERJ-2GEJ102X" 0402S 228,3962 r90 top value=1.0k
R147 "ERJ-2GEJ102X" 0402S 272.69,3955 r90 top value=1.0k
R148 "ERJ-2GEJ102X" 0402S 302.69,3953 r90 top value=1.0k
R149 "ERJ-2GEJ102X" 0402S 333.69,3953 r90 top value=1.0k
R150 "ERJ-2GEJ102X" 0402S 400,4349 r270 top value=1.0k
R151 "ERJ-2GEJ102X" 0402S 365,4349 r270 top value=1.0k
R152 "ERJ-2GEJ102X" 0402S 333,4349 r270 top value=1.0k
R153 "ERJ-2GEJ102X" 0402S 303,4349 r270 top value=1.0k
R154 "ERJ-2GEJ102X" 0402S 273,4349 r270 top value=1.0k
R155 "ERJ-2GEJ102X" 0402S 243,4349 r270 top value=1.0k
R156 "ERJ-2GEJ102X" 0402S 211,4349 r270 top value=1.0k
R157 "ERJ-2GEJ102X" 0402S 181,4349 r270 top value=1.0k
R158 "ERJ-2GEJ102X" 0402S 150,4348 r270 top value=1.0k
R159 "ERJ-2GEJ102X" 0402S 119,4347 r270 top value=1.0k
R160 "CRCW0603300RJNEA" 0603S 82,4297 r90 top value=300
R161 "CRCW0603100RJNEA" 0603S 143,3878 r180 bottom value=100
R162 "CRCW0603100RJNEA" 0603S 342,3717 r180 top value=100
R163 "CRCW120610K0FKEAHP" 1206 265.05,3270.48 r270 top value=10.0k
R164 "CRCW120610K0FKEAHP" 1206 251,3341 r90 bottom value=10.0k
R165 "CRCW0603100RFKEA" 0603S 1365,2959 r90 bottom value=100
R166 "CRCW0603100RFKEA" 0603S 1321,2938 r90 bottom value=100
R167 "CRCW06031M00JNEA" 0603S 134,2399 r0 top value=1.0Meg
R168 "CRCW06033M30JNEA" 0603S 200,2419 r90 top value=3.3Meg
R169 "RT0603BRD07505KL" 0603S 243,2336 r90 top value=505k
R170 "RT0603BRD07505KL" 0603S 243.59,2427.35 r90 top value=505k
R171 "RT0603BRD0716K5L" 0603S 287.59,2426.35 r90 top value=16.5k
R172 "RC0603FR-0747RL" 0603S 378.59,2411.35 r90 top value=47.0
R173 "CRCW060310K0JNEA" 0603S 1757.41,3070.35 r270 top value=10k
R174 "CRCW060310K0JNEA" 0603S 367,3272 r90 top value=10k
R175 "CRCW060310K0JNEA" 0603S 137,3806 r180 bottom value=10k
R176 "CRCW20100000Z0EF" 2010 116,1755.45 r90 top value=0
R177 "CRCW060310M0JNEA" 0603S 1749,3451 r180 top value=10Meg
R178 "CRCW0603100RJNEA" 0603S 77,3891 r90 bottom value=100
R179 "RC2512FK-070RL" FP-RC2512FK-070RL_2512-MFG 959,2953 r270 top value=0
R180 "CRCW0603100RJNEA" 0603S 26,4081 r90 bottom value=100
RT1 "MF51E103F3950" Thermistor_103AT-2 2068.41,4227.35 r270 top value="10.0k ohm"
RT2 "MF51E103F3950" Thermistor_103AT-2 1951,4228 r270 top value="10.0k ohm"
RT3 "MF51E103F3950" Thermistor_103AT-2 1723,4227 r270 top value="10.0k ohm"
RT4 "MF51E103F3950" Thermistor_103AT-2 1828,4227 r270 top value="10.0k ohm"
RT5 "TMP6131DECR" DEC0002A 1732.93,1326.85 r180 top
RT6 "103AT-2" THERMISTOR_103AT-2 101,3505 r90 top value=10k
RT7 "103AT-2" THERMISTOR_103AT-2 413.59,2602.35 r270 top value=10k
S1 "RS-032G05A3-SM RT" SW_RS-032G05A3-SM 2793.41,4374.35 r0 top
S2 "RS-032G05A3-SM RT" SW_RS-032G05A3-SM 2951.41,4634.35 r270 top
U1 "bq76952PFBR" PFB0048A_N 1580.75,3611.08 r270 top
U2 "TLV70433DBVT" DBV0005A_N 2544.41,4032.35 r90 top
U3 "MSPM0G3507SPT" PT0048A-MFG 2308.62,3769.18 r180 top
U4 "TCAN1044DDFRQ1" DDF0008A-MFG 2720.41,3625.35 r0 top
U5 "LM5163DDAR" DDA0008E_M 2003,4854 r270 top
U6 "BQ7721600PWR" PW0024A-MFG 219.43,4106.83 r270 bottom
U7 "BQ34Z100-R2" PW0014A_N 279.59,2630.35 r90 top

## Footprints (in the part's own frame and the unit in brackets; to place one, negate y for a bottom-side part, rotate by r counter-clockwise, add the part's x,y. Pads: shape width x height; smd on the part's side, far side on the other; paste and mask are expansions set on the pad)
0402 [mm] "0402 from SM-752 data"
  rect 0.8x0.6 smd: 1(-0.6,0) 2(0.6,0)
  silkscreen extent -1.22,-0.52 1.22,0.52, body extent -0.55,-0.3 0.55,0.3, height 0.6
0402S [mil] "Based on C0402S footprint from PADS legacy"
  rect 15x24 smd: 1(-20,0) 2(20,0)
  body extent -22,-12 22,12, height 24
0603 [mm] "0603 from SM-752 data"
  rect 1x0.95 smd: 1(-0.8,0) 2(0.8,0)
  silkscreen extent -1.52,-0.69 1.52,0.69, body extent -0.87,-0.47 0.87,0.47, height 1
0603S [mil]
  rect 20x35 smd: 1(-30,0) 2(30,0)
  body extent -34,-19 34,19, height 39
0805_HV [mil] "0805 with 30mil clearance between pads"
  rect 50x63 smd: 1(-40,0) 2(40,0)
  silkscreen extent -74,-40 74,40, body extent -43,-29 43,29, height 57
0805_HV1 [mm] "Custom footprint based on analyzing multiple manufacturer recommendations"
  rrect10% 1x1.25 smd: 1(-1,0) 2(1,0)
  silkscreen extent -0.2,-0.75 0.2,0.75, body extent -1.1,-0.72 1.1,0.73, height 1.45
1206 [mm] "1206 from SM-752 data"
  rect 1.3x1.85 smd: 1(-1.45,0) 2(1.45,0)
  silkscreen extent -2.4,-1.21 2.4,1.21, body extent -1.7,-0.9 1.7,0.9, height 1.35
1206_180 [mm] "1206_180"
  rect 1.1x1.6 smd: 1(-1.7,0) 2(1.7,0)
  silkscreen extent -0.9,-1 0.9,1, body extent -1.75,-0.95 1.75,0.95, height 1.8
1206_190 [mm] "1206_190"
  rect 1.1x1.6 smd: 1(-1.7,0) 2(1.7,0)
  silkscreen extent -0.9,-1 0.9,1, body extent -1.75,-0.95 1.75,0.95, height 1.9
1206L [mm] "1206 from SM-752 data"
  rect 1.1x1.75 smd: 1(-1.35,0) 2(1.35,0)
  silkscreen extent -0.4,-0.77 0.4,0.77, body extent -1.7,-0.9 1.7,0.9, height 1.35
1210 [mm] "1210 from SM-752 data"
  rect 1.3x2.7 smd: 1(-1.45,0) 2(1.45,0)
  silkscreen extent -2.32,-1.57 2.32,1.57, body extent -1.7,-1.35 1.7,1.35, height 1.35
2010 [mm] "Chip Capacitor, Body 5.08x2.54mm, IPC Medium Density"
  rect 1.6x2.7 smd: 1(-2.3,0) 2(2.3,0)
  silkscreen extent -3.42,-1.65 3.42,1.65, body extent -2.73,-1.45 2.73,1.45, height 1.66
2512 [mm] "Chip Resistor, Body 6.3x3.2mm, IPC Medium Density"
  rect 1.3x3.4 smd: 1(-2.95,0) 2(2.95,0)
  silkscreen extent -1.9,-1.6 1.9,1.6, body extent -3.22,-1.67 3.22,1.67, height 0.71
DBV0005A_N [mm] "SOT23, 5-Leads, Body 2.9x1.6mm, Pitch 0.95mm, Lead Span 2.8mm, IPC Medium Density"
  rrect17% 1x0.6 smd: 1(-1.375,0.95) 2(-1.375,0) 3(-1.375,-0.95) 4(1.375,-0.95) 5(1.375,0.95)
  silkscreen extent -0.25,-1.55 0.25,1.55, body extent -1.42,-1.46 1.42,1.46, height 1.09
DDA0008E_M [mm]
  rrect15% 1.65x0.65 smd: 1(-2.825,1.905) 2(-2.825,0.635) 3(-2.825,-0.635) 4(-2.825,-1.905) 5(2.825,-1.905) 6(2.825,-0.635) 7(2.825,0.635) 8(2.825,1.905)
  rrect7% 2.95x4.9 smd paste-1.5 mask-1.5: 9(0,0)
  rrect4% 2.4x3.1 on Top Paste: 9(0,0)
  rrect4% 2.4x3.1 on Top Solder: 9(0,0)
  silkscreen extent -3.42,-2.52 1.4,2.5, body extent -3,-2.45 3,2.45, height 1.57
DDF0008A-MFG [mm]
  rrect22% 1.05x0.45 smd paste+0 mask+0: 1(-1.3,0.975) 2(-1.3,0.325) 3(-1.3,-0.325) 4(-1.3,-0.975) 5(1.3,-0.975) 6(1.3,-0.325) 7(1.3,0.325) 8(1.3,0.975)
  silkscreen extent -2.5,-1.48 0.4,1.48, body extent -1.92,-1.73 1.92,1.73, height 0.25
DEC0002A [mm] "X1SON-2"
  rrect57% 0.35x0.6 smd paste-0.5 mask-0.05: 1(-0.325,0) 2(0.325,0)
  rrect33% 0.3x0.5 on Top Paste: 1S(-0.35,0) 2S(0.35,0)
  body extent -0.5,-0.3 0.5,0.3, height 0.5
FP-RC2512FK-070RL_2512-MFG [mm]
  rrect6% 1.8x4 smd paste+0 mask+0: 1(-3.1,0) 2(3.1,0)
  silkscreen extent -1.83,-1.63 1.83,1.63, body extent -4.1,-2.1 4.1,2.1, height 0.25
Fuse_0678L [mm] "SMD, 2-Leads, Body 9.8x3.05mm"
  rrect3% 3.81x4.06 smd: 1(-4.705,0) 2(4.705,0)
  silkscreen extent -2.4,-1.6 2.4,1.6, body extent -5,-1.59 5,1.59, height 3.18
FUSE_SFK-xx30x [mm] "Fuse"
  rect 7.4x1.2 smd paste+0 mask+0.07: 1(0,2.05) 3(0,-2.05)
  rect 0.75x3 smd paste+0 mask+0.07: 2(-5.575,0)
  Top Layer region: -5.2,1.5 -5.2,-1.5 -3.8,-0.35 -3.8,0.35
  silkscreen extent -4.75,-2.5 4.75,2.5, body extent -4.75,-2.5 4.75,2.5, height 2
HDR1X2 [mm] "Connector; Header; 2 Position"
  rect 1.5x1.5 hole 0.9: 1(0,0)
  round 1.5 hole 0.9: 2(2.54,0)
  silkscreen extent -1.27,-1.27 3.81,1.27
HDR1X4 [mm] "Connector; Header; 4 Position"
  rect 1.5x1.5 hole 0.9: 1(0,0)
  round 1.5 hole 0.9: 2(2.54,0) 3(5.08,0) 4(7.62,0)
  silkscreen extent -1.27,-1.27 8.89,1.27
HDR1X17 [mm] "Connector; Header; 17 Position"
  rect 1.5x1.5 hole 0.9: 1(0,0)
  round 1.5 hole 0.9: 2(2.54,0) 3(5.08,0) 4(7.62,0) 5(10.16,0) 6(12.7,0) 7(15.24,0) 8(17.78,0) 9(20.32,0) 10(22.86,0) 11(25.4,0) 12(27.94,0) 13(30.48,0) 14(33.02,0) 15(35.56,0) 16(38.1,0) 17(40.64,0)
  silkscreen extent -1.27,-1.27 41.91,1.27
HDR2X2 [mm] "Connector; Header; 2x2 Position"
  rect 1.5x1.5 hole 0.9: 1(0,0)
  round 1.5 hole 0.9: 2(0,2.54) 3(2.54,0) 4(2.54,2.54)
  silkscreen extent -1.27,-1.27 3.81,3.81
KTT0002A [mm] "TO-263-2"
  rrect10% 3.82x1.05 smd: 1(-6.9,2.54) 3(-6.9,-2.54)
  rrect1% 7.48x8.55 smd paste-4.2: 2(3.4,0)
  body extent -8.03,-5.08 7.05,5.08, height 4.67
PFB0048A_N [mm] "Thin QFP, 48-Leads, Body 7x7mm, Pitch 0.5mm, IPC Medium Density"
  oval 1.45x0.3 smd: 1(-4.225,2.75) 2(-4.225,2.25) 3(-4.225,1.75) 4(-4.225,1.25) 5(-4.225,0.75) 6(-4.225,0.25) 7(-4.225,-0.25) 8(-4.225,-0.75) 9(-4.225,-1.25) 10(-4.225,-1.75) 11(-4.225,-2.25) 12(-4.225,-2.75) 25(4.225,-2.75) 26(4.225,-2.25) 27(4.225,-1.75) 28(4.225,-1.25) 29(4.225,-0.75) 30(4.225,-0.25) 31(4.225,0.25) 32(4.225,0.75) 33(4.225,1.25) 34(4.225,1.75) 35(4.225,2.25) 36(4.225,2.75)
  oval 0.3x1.45 smd: 13(-2.75,-4.225) 14(-2.25,-4.225) 15(-1.75,-4.225) 16(-1.25,-4.225) 17(-0.75,-4.225) 18(-0.25,-4.225) 19(0.25,-4.225) 20(0.75,-4.225) 21(1.25,-4.225) 22(1.75,-4.225) 23(2.25,-4.225) 24(2.75,-4.225) 37(2.75,4.225) 38(2.25,4.225) 39(1.75,4.225) 40(1.25,4.225) 41(0.75,4.225) 42(0.25,4.225) 43(-0.25,4.225) 44(-0.75,4.225) 45(-1.25,4.225) 46(-1.75,4.225) 47(-2.25,4.225) 48(-2.75,4.225)
  silkscreen extent -4.17,-2.75 2.75,3.58, body extent -4.5,-4.5 4.5,4.5, height 1.07
PT0048A-MFG [mm]
  rrect33% 1.4x0.3 smd paste-1000 mask+0: 1(-4.25,2.75) 2(-4.25,2.25) 3(-4.25,1.75) 4(-4.25,1.25) 5(-4.25,0.75) 6(-4.25,0.25) 7(-4.25,-0.25) 8(-4.25,-0.75) 9(-4.25,-1.25) 10(-4.25,-1.75) 11(-4.25,-2.25) 12(-4.25,-2.75) 25(4.25,-2.75) 26(4.25,-2.25) 27(4.25,-1.75) 28(4.25,-1.25) 29(4.25,-0.75) 30(4.25,-0.25) 31(4.25,0.25) 32(4.25,0.75) 33(4.25,1.25) 34(4.25,1.75) 35(4.25,2.25) 36(4.25,2.75)
  rrect33% 0.3x1.4 smd paste-1000 mask+0: 13(-2.75,-4.25) 14(-2.25,-4.25) 15(-1.75,-4.25) 16(-1.25,-4.25) 17(-0.75,-4.25) 18(-0.25,-4.25) 19(0.25,-4.25) 20(0.75,-4.25) 21(1.25,-4.25) 22(1.75,-4.25) 23(2.25,-4.25) 24(2.75,-4.25) 37(2.75,4.25) 38(2.25,4.25) 39(1.75,4.25) 40(1.25,4.25) 41(0.75,4.25) 42(0.25,4.25) 43(-0.25,4.25) 44(-0.75,4.25) 45(-1.25,4.25) 46(-1.75,4.25) 47(-2.25,4.25) 48(-2.75,4.25)
  silkscreen extent -5.65,-3.6 3.6,3.6, body extent -5.05,-5.05 5.05,5.05, height 0.25
PW0014A_N [mm] "TSOP, 14-Leads, Body 5x4.4mm, Pitch 0.65mm, IPC Medium Density"
  oval 1.4x0.45 smd: 1(-2.95,1.95) 2(-2.95,1.3) 3(-2.95,0.65) 4(-2.95,0) 5(-2.95,-0.65) 6(-2.95,-1.3) 7(-2.95,-1.95) 8(2.95,-1.95) 9(2.95,-1.3) 10(2.95,-0.65) 11(2.95,0) 12(2.95,0.65) 13(2.95,1.3) 14(2.95,1.95)
  silkscreen extent -3.4,-2.55 1.85,2.55, body extent -3.21,-2.5 3.21,2.5, height 1
PW0024A-MFG [mm]
  rrect22% 1.5x0.45 smd paste+0 mask+0: 1(-2.9,3.575) 2(-2.9,2.925) 3(-2.9,2.275) 4(-2.9,1.625) 5(-2.9,0.975) 6(-2.9,0.325) 7(-2.9,-0.325) 8(-2.9,-0.975) 9(-2.9,-1.625) 10(-2.9,-2.275) 11(-2.9,-2.925) 12(-2.9,-3.575) 13(2.9,-3.575) 14(2.9,-2.925) 15(2.9,-2.275) 16(2.9,-1.625) 17(2.9,-0.975) 18(2.9,-0.325) 19(2.9,0.325) 20(2.9,0.975) 21(2.9,1.625) 22(2.9,2.275) 23(2.9,2.925) 24(2.9,3.575)
  silkscreen extent -4.37,-3.95 1.78,3.95, body extent -3.2,-3.9 3.2,3.9, height 1.2
SMB [mil] "Molded Diode, 2-Leads, Body 5.4x3.6mm, IPC Medium Density, based on OnSemi component dimensions"
  rect 85x107.99 smd: 1(-87.01,0) 2(87.01,0)
  silkscreen extent -155,-82 125,82, body extent -106,-71 106,71, height 91
SMC [mil] "Molded Diode, 2-Leads, Body 6.9x5.8mm, IPC Medium Density, based on OnSemi component dimensions and land patterns"
  rect 110x150 smd: 1(-140.49,0) 2(140.49,0)
  silkscreen extent -221,-124 189,123, body extent -156,-116 156,116, height 91
SOD-123 [mm] "On Semi recommended land pattern"
  rect 0.915x1.22 smd: 1(-1.637,0) 2(1.637,0)
  silkscreen extent -2.74,-1.17 2.03,1.17, body extent -1.93,-0.9 1.93,0.9, height 1.35
SOD-123F [mm] "NXP recommended land pattern"
  rect 1.2x1.2 smd paste-0.05: 1(-1.4,0) 2(1.4,0)
  silkscreen extent -2.64,-1.12 2.01,1.12, body extent -1.8,-0.85 1.8,0.85, height 1.2
SOD-323 [mm] "NXP recommended land pattern"
  rect 0.6x0.6 smd paste-0.05: 1(-1.1,0) 2(1.1,0)
  silkscreen extent -2.06,-0.86 1.53,0.86, body extent -1.3,-0.67 1.3,0.68, height 1.1
SOD-523 [mm] "NXP Semiconductor recommended land pattern, nominal STEP model"
  rect 0.8x0.6 smd paste-0.05: 1(-0.55,0) 2(0.55,0)
  silkscreen extent -1.65,-0.66 1.2,0.66, body extent -0.8,-0.4 0.8,0.4, height 0.72
SOT-23 [mm] "SOT23, 3-Leads, Body 2.9x1.3mm, Pitch 0.95mm, Lead Span 2.5mm, IPC Medium Density"
  rrect50% 1x0.6 smd: 1(-1.2,0.95) 2(-1.2,-0.95) 3(1.2,0)
  silkscreen extent -1.62,-1.5 0.7,1.5, body extent -1.16,-1.45 1.21,1.45, height 1
SOT-223 [mm] "SOT223/SC73, 4-Leads, Body 6.5x3.5mm, Pitch 2.3mm, Lead Span 7mm, IPC Medium Density"
  rrect10% 2.4x1 smd: 1(-2.9,2.3) 2(-2.9,0) 3(-2.9,-2.3)
  rrect4% 2.4x3.3 smd: 4(2.9,0)
  silkscreen extent -3.32,-3.35 1.4,3.35, body extent -3.5,-3.25 3.5,3.25, height 1.62
SOT-323 [mm] "Diodes Inc recommended land pattern.  2016-02-24"
  rrect21% 0.6x0.47 smd: 1(-0.95,0.65) 2(-0.95,-0.65) 3(0.95,0)
  silkscreen extent -1.14,-1.22 0.77,1.22, body extent -1.13,-1.13 1.12,1.12, height 1.13
SSOT-6 [mm] "Fairchild"
  rect 1.1x0.7 smd: 1(-1.3,0.95) 2(-1.3,0) 3(-1.3,-0.95) 4(1.3,-0.95) 5(1.3,0) 6(1.3,0.95)
  silkscreen extent -0.85,-1.55 0.25,1.8, body extent -1.5,-1.5 1.5,1.5, height 1.1
SW_RS-032G05A3-SM [mm] "SMT, 2-Leads, Body 6x3.5mm, Pin Spacing 8mm"
  rect 2x2 smd: 1(-4,0) 2(4,0)
  silkscreen extent -3,-1.75 3,1.75, body extent -4,-1.75 4,1.75, height 4.3
Thermistor_103AT-2 [mil] "SEMITEC"
  rect 65x65 hole 35: 1(-50,0)
  round 65 hole 35: 2(50,0)
  body extent -78,-47 79,47, height 338
THERMISTOR_103AT-2 [mil] "SEMITEC"
  rect 65x65 hole 35: 1(-50,0)
  round 65 hole 35: 2(50,0)
  body extent -78,-47 79,47, height 338
UUX_800x620 [mm] "SMD, 2-Leads, Dia 8mm"
  rect 4x2.5 smd: 1(-3.05,0) 2(3.05,0)
  silkscreen extent -4.25,-4.25 4.25,4.25, body extent -4.25,-4.25 4.25,4.25, height 6.51
WE-MAPI_3015 [mm] "SMD, 2-Leads, Body 3x3mm"
  rect 1.3x3.4 smd: 1(-1.05,0) 2(1.05,0)
  silkscreen extent -0.12,-1.7 0.12,1.7, body extent -1.6,-1.6 1.6,1.6, height 1.5
WE-PD_7345 [mm] "SMD Inductor, 2-Leads, Body 7,3x7,3mm"
  rect 1.6x2.2 smd: 1(-3.2,0) 2(3.2,0)
  silkscreen extent -3.65,-3.68 3.61,3.6, body extent -3.65,-3.68 3.65,3.6, height 4.49
WL-SMCW_RED [mm] "WURTH"
  rect 0.8x0.8 smd: 1(-0.8,0) 2(0.8,0)
  silkscreen extent -1.9,-0.8 1.2,0.8, body extent -0.85,-0.45 0.85,0.45, height 0.8

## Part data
C1 C2 C3 C4 C5 C6 C7 C8 C9 C10 C11 C12 C13 C14 C20 C21 C22: library part CMP-0007145-4, "CAP, CERM, 0.22 uF, 50 V, +/- 10%, X7R, AEC-Q200 Grade 1, 0603", Cap_Case=0603, Manufacturer=MuRata, Supplier Part Number 1=490-5402-1-ND, TempCo=X7R, Tolerance_%=10%, Value1=Unknown, Value2=50V, ValueDisplayed=0.22uF
C15: library part CMP-0008804-2, "CAP, CERM, 2.2 uF, 100 V, +/- 10%, X7R, 1206_190", Cap_Case=1206, Manufacturer="Samsung Electro-Mechanics", TempCo=X7R, Tolerance_%=10%, Value1=Unknown, Value2=100V, ValueDisplayed=2.2uF
C16 C17 C24 C25 C33 C84: library part CMP-0007237-4, "CAP, CERM, 100 pF, 100 V, +/- 5%, C0G/NP0, 0603", Cap_Case=0603, Manufacturer=MuRata, Supplier Part Number 1=490-1351-1-ND, TempCo=C0G/NP0, Tolerance_%=5%, Value1=Unknown, Value2=100V, ValueDisplayed=100pF
C18: library part CMP-0007040-4, "CAP, CERM, 1 uF, 25 V, +/- 10%, X7R, 0603", Cap_Case=0603, Manufacturer=TDK, Supplier Part Number 1=445-5956-1-ND, TempCo=X7R, Tolerance_%=10%, Value1=Unknown, Value2=25V, ValueDisplayed=1uF
C19 C42: library part CMP-0064934-4, "CAP, CERM, 2.2 uF, 16 V,+/- 10%, X7R, 0603", Cap_Case=0603, Manufacturer="Taiyo Yuden", Supplier Part Number 1=587-4864-1-ND, TempCo=X7R, Tolerance_%=10%, Value1=Unknown, Value2=16V, ValueDisplayed=2.2uF
C23 C26 C32 C35 C37 C39: library part CMP-0007455-4, "CAP, CERM, 470 pF, 50 V, +/- 10%, X7R, 0603", Cap_Case=0603, Manufacturer=MuRata, Supplier Part Number 1=490-1489-1-ND, TempCo=X7R, Tolerance_%=10%, Value1=Unknown, Value2=50V, ValueDisplayed=470pF
C27 C28 C29 C43 C44 C45 C46 C81 C82 C83 C86: library part CMP-0007434-4, "CAP, CERM, 0.1 uF, 50 V, +/- 10%, X7R, 0603", Cap_Case=0603, Manufacturer=MuRata, Supplier Part Number 1=490-1519-1-ND, TempCo=X7R, Tolerance_%=10%, Value1=Unknown, Value2=50V, ValueDisplayed=0.1uF
C30 C31: library part CMP-0007136-5, "CAP, CERM, 1 uF, 16 V, +/- 10%, X7R, AEC-Q200 Grade 1, 0603", Cap_Case=0603, Manufacturer=MuRata, Supplier Part Number 1=490-5241-6-ND, TempCo=X7R, Tolerance_%=10%, Value1=Unknown, Value2=16V, ValueDisplayed=1uF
